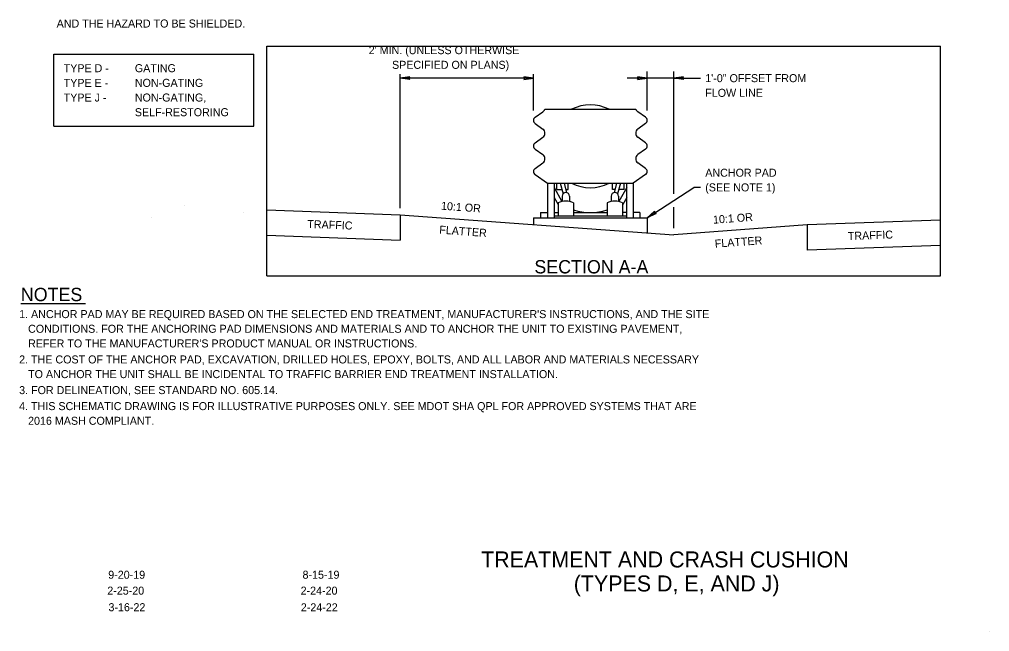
# Model space of a CAD drawing. Extents: x 12.3 to 19.6, y 6 to 16.1.
# Drawn here: x 12.35 to 19.62, y 5.98 to 10.58 of the extents above; entities that cross this region are included whole.
import ezdxf

# ---------------------------------------------------------------- set-up
doc = ezdxf.new("R2010")
doc.units = 0
for name, color, linetype in [('Default', 7, 'Continuous'), ('DETL-DIMS', 7, 'Continuous'), ('DETL-LINE', 7, 'Continuous'), ('DETL-NOTE', 7, 'Continuous'), ('DETL-TITL', 7, 'Continuous'), ('TTLB-TEXT', 7, 'Continuous')]:
    doc.layers.add(name, color=color, linetype=linetype)

msp = doc.modelspace()

# ---------------------------------------------------------------- linework, layer by layer
at = {"layer": 'Default'}
for p, q in [((14.2023, 10.3744), (19.2537, 10.3744)), ((14.2023, 8.6518), (14.2023, 10.3744)), ((19.2537, 8.6518), (19.2537, 10.3744)), ((14.2023, 8.6518), (19.2537, 8.6518))]:
    msp.add_line(p, q, dxfattribs=at)
at = {"layer": 'DETL-DIMS'}
for p, q in [((17.0537, 9.8927), (17.0537, 10.1844)), ((17.2537, 9.2678), (17.2537, 10.1844)), ((15.2023, 9.1608), (15.2023, 10.1644)), ((15.2752, 10.145), (15.2023, 10.1344)), ((16.2023, 10.1344), (15.2023, 10.1344)), ((15.2752, 10.1238), (15.2023, 10.1344)), ((15.2752, 10.145), (15.2661, 10.1344)), ((15.2752, 10.1238), (15.2661, 10.1344)), ((16.1294, 10.145), (16.2023, 10.1344)), ((16.1294, 10.145), (16.1385, 10.1344)), ((16.1294, 10.1238), (16.2023, 10.1344)), ((16.1294, 10.1238), (16.1385, 10.1344)), ((16.2023, 9.8927), (16.2023, 10.1644)), ((17.0537, 10.1344), (16.9037, 10.1344)), ((16.9808, 10.145), (17.0537, 10.1344)), ((16.9808, 10.145), (16.9899, 10.1344)), ((16.9808, 10.1238), (17.0537, 10.1344)), ((16.9808, 10.1238), (16.9899, 10.1344)), ((17.2537, 10.1344), (17.0537, 10.1344)), ((17.3266, 10.145), (17.2537, 10.1344)), ((17.2537, 10.1344), (17.4537, 10.1344)), ((17.3266, 10.1238), (17.2537, 10.1344)), ((17.3266, 10.145), (17.3175, 10.1344)), ((17.3266, 10.1238), (17.3175, 10.1344)), ((17.0537, 9.0877), (17.4037, 9.3153)), ((17.4537, 9.3153), (17.4037, 9.3153)), ((17.2537, 9.0108), (17.2537, 9.1678)), ((17.109, 9.1363), (17.0537, 9.0877)), ((17.1206, 9.1186), (17.0537, 9.0877)), ((17.109, 9.1363), (17.1072, 9.1225)), ((17.1206, 9.1186), (17.1072, 9.1225))]:
    msp.add_line(p, q, dxfattribs=at)
for points in [[(15.2752, 10.1238), (15.2023, 10.1344), (15.2752, 10.145), (15.2661, 10.1344)], [(16.1294, 10.1238), (16.2023, 10.1344), (16.1294, 10.145), (16.1385, 10.1344)], [(16.9808, 10.1238), (17.0537, 10.1344), (16.9808, 10.145), (16.9899, 10.1344)], [(17.3266, 10.1238), (17.2537, 10.1344), (17.3266, 10.145), (17.3175, 10.1344)], [(17.1206, 9.1186), (17.0537, 9.0877), (17.109, 9.1363), (17.1072, 9.1225)]]:
    msp.add_lwpolyline(points, close=True, dxfattribs=at)
at = {"layer": 'DETL-LINE'}
for p, q in [((16.288, 9.901), (16.9679, 9.901)), ((16.2147, 9.841), (16.273, 9.8827)), ((17.0413, 9.841), (16.9829, 9.8827)), ((16.2147, 9.7944), (16.273, 9.7527)), ((17.0413, 9.7944), (16.9829, 9.7527)), ((16.2147, 9.6494), (16.273, 9.691)), ((17.0413, 9.6494), (16.9829, 9.691)), ((16.2147, 9.6027), (16.273, 9.561)), ((17.0413, 9.6027), (16.9829, 9.561)), ((16.2147, 9.4577), (16.273, 9.4994)), ((17.0413, 9.4577), (16.9829, 9.4994)), ((16.2147, 9.411), (16.3057, 9.346)), ((17.0413, 9.411), (16.9503, 9.346)), ((16.3057, 9.346), (16.9503, 9.346)), ((16.3057, 9.346), (16.3057, 9.0877)), ((16.3557, 9.346), (16.3557, 9.0877)), ((16.3557, 9.314), (16.4149, 9.2095)), ((16.3757, 9.2994), (16.3757, 9.346)), ((16.4027, 9.346), (16.424, 9.2678)), ((16.4312, 9.346), (16.4505, 9.2753)), ((16.4624, 9.2994), (16.4624, 9.346)), ((16.7937, 9.2994), (16.7937, 9.346)), ((16.8249, 9.346), (16.8056, 9.2753)), ((16.8534, 9.346), (16.8321, 9.2678)), ((16.9004, 9.314), (16.8412, 9.2095)), ((16.8804, 9.2994), (16.8804, 9.346)), ((16.9003, 9.346), (16.9003, 9.0877)), ((16.9503, 9.346), (16.9503, 9.0877)), ((16.3557, 9.239), (16.3857, 9.186)), ((16.3757, 9.2994), (16.4154, 9.2994)), ((16.4157, 9.2494), (16.4157, 9.2097)), ((16.4439, 9.2994), (16.4624, 9.2994)), ((16.4724, 9.2494), (16.4724, 9.2097)), ((16.7836, 9.2494), (16.7836, 9.2097)), ((16.8122, 9.2994), (16.7937, 9.2994)), ((16.8403, 9.2494), (16.8403, 9.2097)), ((16.8804, 9.2994), (16.8407, 9.2994)), ((16.9004, 9.239), (16.8704, 9.186)), ((13.5841, 9.1822), (13.5841, 9.1822)), ((13.5841, 9.1822), (13.5841, 9.1822)), ((16.3857, 9.1994), (16.3857, 9.1027)), ((16.5024, 9.1994), (16.5024, 9.1027)), ((16.7536, 9.1994), (16.7536, 9.1027)), ((16.8703, 9.1994), (16.8703, 9.1027)), ((13.3359, 9.0906), (13.3359, 9.0906)), ((14.0314, 9.1255), (14.0314, 9.1255)), ((14.0314, 9.1255), (14.0314, 9.1255)), ((14.0314, 9.1255), (14.0314, 9.1255)), ((14.2023, 9.1474), (15.2023, 9.1108)), ((15.2023, 9.1108), (15.2023, 8.9207)), ((15.2023, 9.1108), (17.2537, 8.9608)), ((16.2557, 9.126), (16.2557, 9.0877)), ((16.2557, 9.126), (16.3057, 9.126)), ((16.3557, 9.126), (16.3857, 9.126)), ((16.3557, 9.1027), (16.9003, 9.1027)), ((16.5024, 9.126), (16.7536, 9.126)), ((16.9003, 9.126), (16.8703, 9.126)), ((17.0003, 9.126), (16.9503, 9.126)), ((17.0003, 9.126), (17.0003, 9.0877)), ((16.2023, 9.0877), (17.0537, 9.0877)), ((16.2023, 9.0877), (16.2023, 9.0377)), ((17.0537, 9.0877), (17.0537, 8.9755)), ((18.2537, 9.034), (17.2537, 8.9608)), ((19.2537, 9.0706), (18.2537, 9.034)), ((18.2537, 9.034), (18.2537, 8.8438)), ((14.2023, 8.9573), (15.2023, 8.9207)), ((19.2537, 8.8804), (18.2537, 8.8438))]:
    msp.add_line(p, q, dxfattribs=at)
for centre, radius, start, end in [((16.2522, 9.9151), 0.0385, 302.80335, 338.61808), ((16.628, 9.6237), 0.3107, 63.21522, 116.78465), ((17.0038, 9.9151), 0.0385, 201.38192, 237.19665), ((16.2304, 9.8177), 0.0281, 123.93623, 236.06377), ((17.0256, 9.8177), 0.0281, 303.93623, 56.06377), ((16.247, 9.7219), 0.0404, 310.18223, 49.81777), ((17.009, 9.7219), 0.0404, 130.18223, 229.81777), ((16.2304, 9.626), 0.0281, 123.93623, 236.06377), ((17.0256, 9.626), 0.0281, 303.93623, 56.06377), ((16.247, 9.5302), 0.0404, 310.18223, 49.81777), ((17.009, 9.5302), 0.0404, 130.18223, 229.81777), ((16.2304, 9.4344), 0.0281, 123.93623, 236.06377), ((17.0256, 9.4344), 0.0281, 303.93623, 56.06377), ((16.628, 9.6234), 0.3107, 243.21535, 296.78478), ((16.444, 9.2477), 0.0284, 3.47016, 176.52984), ((16.8119, 9.2477), 0.0284, 3.47016, 176.52984), ((16.444, 9.0784), 0.1343, 64.25065, 115.74935), ((16.8119, 9.0784), 0.1343, 64.25065, 115.74935), ((16.628, 9.5305), 0.4045, 251.90735, 288.09265)]:
    msp.add_arc(centre, radius, start, end, dxfattribs=at)
at = {"layer": 'DETL-NOTE'}
for p, q in [((12.6053, 10.3142), (14.1046, 10.3142)), ((12.6053, 9.7742), (12.6053, 10.3142)), ((14.1046, 9.7742), (14.1046, 10.3142)), ((12.6053, 9.7742), (14.1046, 9.7742)), ((12.3592, 8.4452), (12.844, 8.4452))]:
    msp.add_line(p, q, dxfattribs=at)
at = {"layer": 'DETL-TITL'}
msp.add_line((16.2087, 8.6518), (17.2473, 8.6518), dxfattribs=at)
at = {"layer": 'TTLB-TEXT'}
msp.add_line((19.6208, 5.9844), (19.6208, 5.9844), dxfattribs=at)

# ---------------------------------------------------------------- texts
at = {"layer": 'DETL-NOTE'}
for s, p in [(' AND THE HAZARD TO BE SHIELDED.', (12.6053, 10.5142)), ('TYPE D -', (12.6803, 10.1792)), ('GATING ', (13.2138, 10.1792)), ('TYPE E -', (12.6803, 10.0692)), ('NON-GATING  ', (13.2138, 10.0692)), ('TYPE J -', (12.6803, 9.9592)), ('NON-GATING,', (13.2138, 9.9592)), ('SELF-RESTORING', (13.2138, 9.8492))]:
    msp.add_text(s, height=0.06, dxfattribs=at).set_placement(p)
for s, height, rotation, p in [("2' MIN. (UNLESS OTHERWISE", 0.06, 360, (14.9667, 10.3144)), ('SPECIFIED ON PLANS)', 0.06, 360, (15.1415, 10.2044)), ('1\'-0" OFFSET FROM', 0.06, 360, (17.4895, 10.1044)), ('FLOW LINE', 0.06, 360, (17.4895, 9.9944)), ('ANCHOR PAD', 0.06, 360, (17.4895, 9.3953)), ('(SEE NOTE 1)', 0.06, 360, (17.4895, 9.2853)), ('10:1 OR', 0.06, 355.81766, (15.5072, 9.1487)), ('10:1 OR', 0.06, 4.18234, (17.5499, 9.0426)), ('TRAFFIC', 0.06, 357.90398, (14.5056, 9.0113)), ('FLATTER', 0.06, 355.81766, (15.4941, 8.9692)), ('FLATTER', 0.06, 4.18234, (17.563, 8.8631)), ('TRAFFIC', 0.06, 2.09602, (18.5592, 8.92)), ('NOTES', 0.1, 360, (12.3592, 8.4623)), ("1. ANCHOR PAD MAY BE REQUIRED BASED ON THE SELECTED END TREATMENT, MANUFACTURER'S INSTRUCTIONS, AND THE SITE ", 0.06, 360, (12.3466, 8.3352)), ('   CONDITIONS. FOR THE ANCHORING PAD DIMENSIONS AND MATERIALS AND TO ANCHOR THE UNIT TO EXISTING PAVEMENT,', 0.06, 360, (12.3466, 8.2252)), ("   REFER TO THE MANUFACTURER'S PRODUCT MANUAL OR INSTRUCTIONS.", 0.06, 360, (12.3466, 8.1152)), ('2. THE COST OF THE ANCHOR PAD, EXCAVATION, DRILLED HOLES, EPOXY, BOLTS, AND ALL LABOR AND MATERIALS NECESSARY', 0.06, 360, (12.3466, 7.9952)), ('   TO ANCHOR THE UNIT SHALL BE INCIDENTAL TO TRAFFIC BARRIER END TREATMENT INSTALLATION.', 0.06, 360, (12.3466, 7.8852)), ('3. FOR DELINEATION, SEE STANDARD NO. 605.14.', 0.06, 360, (12.3466, 7.7652)), ('4. THIS SCHEMATIC DRAWING IS FOR ILLUSTRATIVE PURPOSES ONLY. SEE MDOT SHA QPL FOR APPROVED SYSTEMS THAT ARE', 0.06, 360, (12.3466, 7.6452)), ('   2016 MASH COMPLIANT.', 0.06, 360, (12.3466, 7.5352))]:
    msp.add_text(s, height=height, rotation=rotation, dxfattribs=at).set_placement(p)
at = {"layer": 'DETL-TITL'}
msp.add_text('SECTION A-A', height=0.1, rotation=360, dxfattribs=at).set_placement((16.2087, 8.6701))
at = {"layer": 'TTLB-TEXT'}
for s, height, p in [('TREATMENT AND CRASH CUSHION ', 0.12, (15.8096, 6.4654)), ('(TYPES D, E, AND J)', 0.12, (16.5037, 6.2854)), ('2-25-20', 0.06, (13.0072, 6.2616)), ('2-24-20', 0.06, (14.4563, 6.2616)), ('3-16-22', 0.06, (13.0161, 6.1373)), ('2-24-22', 0.06, (14.4579, 6.1364))]:
    msp.add_text(s, height=height, dxfattribs=at).set_placement(p)
for s, p in [('9-20-19', (13.0144, 6.3808)), ('8-15-19', (14.4708, 6.3808))]:
    msp.add_text(s, height=0.06, rotation=360, dxfattribs=at).set_placement(p)

doc.saveas('drawing.dxf')
